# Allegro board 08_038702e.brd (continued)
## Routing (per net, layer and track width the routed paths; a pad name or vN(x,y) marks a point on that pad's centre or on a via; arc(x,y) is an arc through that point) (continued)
VBUS: length 39.7
  L18_SIG w0.203: v1(87.68,36.43) 86.79,36.43 85.9,37.32 85.9,38.21 84.76,39.35 78.03,39.35 72.19,45.19 v1(69.78,45.19)
  BOTTOM w0.14: P1.A1 89.17,34.94 89.17,32 DS1.A
  BOTTOM w0.203: v1(87.68,36.43) 87.81,36.43 89.08,35.16 P1.A1 ; D1.2 69.34,44.76 v1(69.78,45.19)
  BOTTOM w0.381: P1.B1 P1.A1
VCC-1P35: length 98.5
  TOP w0.254: v1(56.99,34.61) 57.22,34.84 C118.1 ; C108.1 49.84,30.21 49.33,29.7 49.33,28.78 v1(49.79,28.31) ; 60.5,45.45 60.12,44.94 60.12,44.18 59.38,43.43 59.14,43.4 v1(57.07,43.4) ; v1(49.79,45.08) 49.72,45 C115.1 ; C116.1 57.96,45.83 v1(57.2,45.07) ; v1(49.79,43.48) 49.67,43.35 C112.1 ; v1(16.18,16.62) 16.55,16.62 16.59,16.66 17.41,16.66 18.59,15.48 39.17,15.48 40.69,17 49.11,17 v1(49.79,16.31) ; C117.1 57.14,38.53 v1(56.99,38.68)
  TOP w0.305: v1(56.19,16.29) 56.38,16.1 C91.1 ; v1(56.97,28.29) 57.84,27.41 C88.1 ; v1(49.79,28.31) 49.59,28.11 C96.1 ; C89.1 58.09,22.46 57.58,21.95 57.27,21.95 C95.1 57.02,21.89 v1(56.99,21.91) ; v1(49.79,20.31) 49.72,20.24 C92.1 ; C97.1 49.67,26.59 49.73,26.65 v1(49.79,26.65) ; C109.1 49.7,34.59 v1(49.79,34.68) ; C94.1 56.31,24.43 ; 56.31,24.43 56.88,25 C87.1 ; 56.31,24.43 v1(56.19,24.31)
  TOP w0.508: v1(53.14,58.15) 53.77,58.15 54.28,58.66 C100.1 54.28,58.91 53.77,59.42 v1(53.14,59.42) ; v1(56.99,19.51) 57.02,19.54 58.47,19.54 ; 39.42,58.78 38.91,58.78 38.66,58.53 v1(38.65,58.53) ; 39.42,58.78 C120.1 ; 39.42,58.78 v1(39.42,57.89) ; v1(49.79,16.31) 49.04,15.56 C192.1 49.07,15.18 49.07,14.08 48.44,13.44 E3.2 ; v1(59.23,38.59) 58.73,39.1 58.47,39.1
  L15_SIG w0.406: v1(53.14,58.15) 53.52,58.15 53.9,58.53 53.9,59.04 53.52,59.42 v1(53.14,59.42) 53.14,59.67 52.63,60.18 49.84,60.18 48.95,61.07 v1(48.31,61.07) v1(47.8,61.07)
  BOTTOM w0.203: v1(50.59,33.94) 50.66,33.94 U3.B2 ; U2.C1 v1(49.79,17.91) ; U2.E9 v1(56.99,19.51) ; U3.A8 55.94,33.33 v1(55.94,33.08) ; U3.A1 49.79,33.08 v1(49.79,33.01) ; v6(56.99,17.94) 56.97,17.94 U2.C9 ; U3.G7 55.36,38.65 v1(55.36,38.71) ; U2.K8 v1(56.19,24.31) ; v1(56.99,34.61) 56.99,34.68 U3.C9 ; U3.C1 v1(49.79,34.68) ; U3.R9 56.99,45.08 57.19,45.08 v1(57.2,45.07) ; U2.G7 v1(55.39,21.11) ; U3.N1 v1(49.79,43.48) ; U3.K2 v1(50.59,41.08) ; U3.H9 v1(56.99,38.68) ; U3.R1 v1(49.79,45.08) ; U2.B2 v1(50.59,17.11) ; U2.R1 v1(49.79,28.31) ; U2.H9 v1(56.99,21.91) ; U2.H2 v1(50.59,21.91) ; v1(56.99,35.54) 56.93,35.54 U3.D9 ; U3.H2 v1(50.59,38.68) ; U2.D9 v1(56.99,18.71) ; U2.N1 49.86,26.65 v1(49.79,26.65) ; U2.N9 v1(56.99,26.71) ; U2.A8 56.19,16.31 v1(56.19,16.29) ; U2.D2 v1(50.59,18.71) ; v1(50.59,35.41) 50.59,35.48 U3.D2 ; U3.K8 v1(56.19,41.08) ; U3.F1 v1(49.79,37.08) ; U2.A1 v1(49.79,16.31) ; U3.E9 v1(56.99,36.28) ; U2.K2 v1(50.59,24.31) ; v1(57.07,43.4) 57.02,43.35 57.01,43.35 56.74,43.08 U3.N9 ; U2.R9 v1(56.97,28.29) ; U2.F1 v1(49.79,20.31)
  BOTTOM w0.254: v1(48.31,61.07) v1(47.8,61.07) 48.06,60.81 48.06,60.36 U14.1
  BOTTOM w0.508: v1(16.18,16.62) 16.56,17 R134.2
VCC-3P3V: length 12.7
  TOP w0.406: C196.1 21.26,59.54 v1(22.02,60.31) ; v1(23.29,60.56) 23.29,60.05 23.61,59.73 E7.2
  TOP w0.508: C196.1 22.06,59.51 v1(22.53,59.04) 23.04,59.54 E7.2
  L17_SIG w0.406: v1(45.39,61.2) 44.5,60.31 v1(42.6,60.31)
  BOTTOM w0.203: 44.46,60.22 R221.1
  BOTTOM w0.254: U14.10 44.46,60.22
  BOTTOM w0.508: v1(42.6,60.31) R222.1 R221.1 ; C43.2 v1(45.39,61.2) ; R178.1 v1(11.86,55.1)
VCC-3P3V-IO: length 35.2
  TOP w0.203: U1.V8 v1(29.22,36.59) ; U1.W8 v1(28.22,36.59) ; U1.U8 v1(30.22,36.59) ; U1.V12 v1(29.22,32.59) ; U1.V14 v1(29.22,29.59)
  TOP w0.305: U11.17 v1(4.64,13.84) ; v1(7.16,10.52) 7.16,11.54 7.55,11.92 U11.21 ; R168.1 v1(34.98,48.62) ; U15.21 19.99,52.69 v1(19.61,53.07) 19.73,53.19 U15.20 ; R167.1 v1(33.33,48.62)
  TOP w0.406: S1.3 v1(4.67,7.81) ; J3.4 v1(1.98,27.26) ; D4.A 43.27,48.75
  TOP w0.508: R8.1 42.47,11.54 41.84,10.9 v1(41.84,9.63) ; 43.27,48.75 v1(43.99,48.75) ; E8.2 31.23,58.59 31.04,58.4 v1(31.04,57.77) ; C41.1 v1(7.16,10.52) ; C197.1 v1(27.57,58.87)
  L3_SIG w0.406: v1(3.61,17) 2.21,18.4 2.21,21.19 3.61,22.59 3.61,25.64 v1(1.98,27.26)
  BOTTOM w0.406: v1(3.23,10.27) 3.86,10.9
  BOTTOM w0.508: C184.1 20.03,53.49 v1(19.61,53.07) ; 3.86,10.9 R109.1 ; C42.1 v1(3.61,17) R4.1 ; C57.1 v1(3.23,9.25)
VCCO-DDR: length 21.2
  TOP w0.203: U1.W22 v1(28.22,21.59) ; U1.H25 v1(40.22,18.59) ; U1.J22 v1(39.22,21.59) ; U1.V25 v1(29.22,18.59) ; U1.N20 v1(35.22,23.59) ; U1.T21 v1(31.22,22.59) ; U1.R24 v1(32.22,19.59) ; U1.M23 v1(36.22,20.59) ; U1.L26 v1(37.22,17.59)
  TOP w0.305: v1(51.61,14.84) C193.1 51.53,15.64 50.98,15.09 v1(50.98,14.84)
  TOP w0.508: C138.1 50.22,5.44 v1(49.46,4.68) ; v1(52.5,4.68) 52.5,4.81 v1(52.76,5.06) 52.76,5.57 C139.1 ; E2.2 v1(49.52,4.11)
  BOTTOM w0.305: C130.1 35.07,23.73 v1(35.22,23.59)
  BOTTOM w0.508: C135.1 v1(19.61,22.97) ; C132.1 v1(19.61,18.4) ; C126.1 v1(27.99,16.49) ; C127.1 v1(36.88,16.36) ; C137.1 v1(34.09,16.49) ; C131.1 v1(41.45,16.36) ; C128.1 v1(29.52,16.49) ; C136.1 v1(38.41,16.36) ; C129.1 v1(32.56,16.49) ; C121.1 v1(31.04,16.49)
VCCO_1P8V: length 14.4
  TOP w0.203: U1.H15 v1(40.22,28.59) ; U1.E14 v1(43.22,29.59) ; U1.B13 v1(46.22,31.59) ; U1.J12 v1(39.22,32.59) ; U1.F11 v1(42.22,33.59) ; U1.A16 v1(47.22,27.59)
  TOP w0.305: 11.8,49.77 v1(14.28,49.77) ; v1(14.28,49.77) 14.4,49.89 v1(14.91,49.89) ; v1(14.28,49.77) v1(14.66,49.38)
  BOTTOM w0.305: C70.1 v1(29.9,44.94) ; C93.1 v1(36.25,44.94) ; C71.1 v1(45.52,44.94) ; C250.1 v1(42.22,30.59) ; C37.1 v1(45.22,30.59) ; C249.1 v1(39.22,30.59) ; C90.1 v1(32.95,44.94) ; C72.1 v1(42.47,44.94) ; C98.1 v1(39.42,44.94)
VCCO_1P8V_EN: length 4.1
  TOP w0.14: U7.24 10.58,46.86 10.34,47.1 10.34,49.7 10.4,49.77
VCCO_12: length 11.7
  TOP w0.203: U1.AA16 v1(26.22,27.59) ; U1.AB13 v1(25.22,31.59) ; U1.AD17 v1(23.22,26.59) ; U1.AC10 v1(24.22,34.59) ; U1.AF11 v1(21.22,33.59) ; U1.AE14 v1(22.22,29.59)
  TOP w0.254: v1(14.62,37.07) 14.56,37.13 14.15,37.13
  TOP w0.406: 14.29,37.07 14.29,37.34 Q11.4 ; 14.29,37.07 v1(14.62,37.07) v1(15.04,37.07) ; 14.29,37.07 Q11.PAD2
  BOTTOM w0.254: v1(14.62,37.07) v1(15.04,37.07)
  BOTTOM w0.508: C160.1 v1(19.61,21.44) ; C144.1 v1(19.61,28.94) ; v1(23.17,16.36) 23.55,15.98 C153.1 ; C157.1 v1(26.21,16.49) ; C146.1 v1(19.61,19.92) ; C111.1 v1(19.61,24.49)
VCCO_12_13_EN: length 30.8
  TOP w0.14: v1(6.78,49) 8.08,47.71 U7.29 ; v1(14.91,36.05) 14.38,35.52 Q11.3 ; Q9.3 17.34,35.18 16.94,34.78 16.56,34.78 v1(16.18,34.4)
  L17_SIG w0.095: 15.55,35.5 16.18,36.13 16.18,36.33 17.03,37.18 17.03,37.46 16.83,37.66 16.83,38.22 17.2,38.59 17.2,42.02 16.44,42.78 12.63,42.78 12.12,43.29 12.12,44.43 11.61,44.94 10.85,44.94 v1(6.78,49) ; 15.55,35.5 15.46,35.5 v1(14.91,36.05) ; 15.55,35.5 15.55,35.03 v1(16.18,34.4)
VCCO_13: length 23.3
  TOP w0.203: U1.Y19 v1(27.22,24.59) ; U1.AE24 v1(22.22,19.59) ; U1.AF21 v1(21.22,22.59) ; U1.AB23 v1(25.22,20.59) ; U1.AC20 v1(24.22,23.59) ; U1.AA26 v1(26.22,17.59)
  TOP w0.254: v1(19.61,34.4) 19.61,36.43 18.15,37.89 ; Q9.PAD2 17.34,37.2 Q9.4 17.55,37.89
  TOP w0.305: 17.2,37.89 18.15,37.89
  BOTTOM w0.254: v1(6.53,21.57) 6.52,21.58 5.14,21.58 4.96,21.4 U21.1 ; 5.26,18.52 3.1,18.52 R57.1
  BOTTOM w0.305: U21.1 4.96,20.34 5.51,19.79 R58.1 ; v1(6.53,21.57) 6.28,21.32 C243.2
  BOTTOM w0.406: 5.26,18.52 5.51,18.78 R58.1 ; 20.12,31.73 v1(19.61,31.73)
  BOTTOM w0.508: C167.1 v1(19.61,26.02) ; C171.1 v1(19.61,34.4) ; C169.1 20.75,15.98 v1(21.13,16.36) ; C186.1 v1(24.69,16.36) ; C185.1 v1(19.61,16.36)
VCCO_33_34: length 22.9
  TOP w0.203: U1.G8 v1(41.22,36.59) ; U1.A6 v1(47.22,38.59) ; U1.K9 v1(38.22,35.59) ; U1.F1 v1(42.22,43.59) ; U1.E4 v1(43.22,40.59) ; v1(18.72,41.64) 18.59,41.51 ; U1.D7 v1(44.22,37.59) ; U1.B3 v1(46.22,41.59) ; U1.J2 v1(39.22,42.59) ; U1.M3 v1(36.22,41.59) ; U1.L6 v1(37.22,38.59) ; U1.C10 v1(45.22,34.59) ; U1.H5 v1(40.22,39.59)
  TOP w0.305: Q10.4 17.2,41 17.71,41.51 18.59,41.51 ; C246.1 54.66,29.32 55.26,29.92 v1(55.68,29.92) U22.14
  TOP w0.508: v1(47.04,44.94) 47.3,45.19 C145.1 ; v1(19.23,41.64) v1(18.72,41.64)
  BOTTOM w0.203: C147.1 v1(47.55,16.36)
  BOTTOM w0.305: C27.1 v1(40.95,44.94) ; C15.1 v1(37.9,44.94) ; C17.1 v1(34.6,44.94) ; C31.1 v1(43.99,44.94) ; C154.1 v1(34.22,38.59) ; C18.1 v1(31.42,44.94)
  BOTTOM w0.508: C114.1 v1(28.37,44.94) ; v1(44.5,16.36) 44.5,15.98 C110.1 ; C28.1 v1(26.85,44.94) ; C99.1 v1(25.33,44.94)
VCCO_33_34_EN: length 24.4
  TOP w0.14: v1(7.16,51.16) 7.8,50.53 7.8,48.88 8.58,48.09 8.58,47.62 8.57,47.61 8.57,46.72 8.58,46.71 U7.28 ; v1(17.58,39.73) 17.39,39.54 Q10.3
  L17_SIG w0.095: v1(7.16,51.16) 8.56,49.77 8.56,48.11 9.36,47.31 10.13,47.31 10.72,46.72 13.64,46.72 16.56,43.8 16.56,43.16 17.71,42.02 17.71,39.86 v1(17.58,39.73)
VCCPCOM-1P8V: length 90.2
  TOP w0.203: U1.G18 v1(41.22,25.59) ; U1.M10 v1(36.22,34.59) ; U1.U9 v1(30.22,35.59) ; U1.T10 v1(31.22,34.59) ; U1.E24 v1(43.22,19.59) ; U1.F21 v1(42.22,22.59) ; U1.K18 v1(38.22,25.59) ; U1.A26 v1(47.22,17.59) ; U1.R9 v1(32.22,35.59) ; U1.V6 v1(29.22,38.59) ; U1.B23 v1(46.22,20.59) ; U1.V10 v1(29.22,34.59) ; U15.14 v1(22.16,56.1) ; U1.R19 v1(32.22,24.59) ; U1.U19 v1(30.22,24.59) ; U1.L19 v1(37.22,24.59) ; U1.C20 v1(45.22,23.59) ; U1.D17 v1(44.22,26.59) ; U1.P10 v1(33.22,34.59) ; U1.T8 v1(31.22,36.59) ; U1.N19 v1(35.22,24.59) ; U15.11 v1(23.66,56.1) ; U1.P8 v1(33.22,36.59) ; U1.N9 v1(35.22,35.59)
  TOP w0.305: C180.1 4.62,49.26 5.51,50.15 v1(6.02,50.15) ; C180.1 4.75,49 5.01,49.26 v1(6.02,49.26) ; C180.1 4.62,48.88 5.01,48.5 5.89,48.5 v1(6.02,48.62) ; U11.5 v1(10.58,15.34) 10.95,14.97 C54.1 ; U15.8 25.68,54.69 v1(25.96,54.97) ; v1(67.62,52.81) 67.87,52.81 68.12,53.07 68.63,53.07 v1(68.76,53.19) 68.54,53.42 68.52,53.42 68.22,53.71 68.22,53.86 68.12,53.96 68.12,55.1 68.62,55.59 U13.B4 ; Q12.1 v1(9.83,50.78) ; v1(24.94,49.89) 24.66,50.17 U15.32 ; R194.1 42.22,14.59 42.22,16.24 42.43,16.45 42.89,16.45 v1(42.98,16.36) ; Q12.2 v1(9.83,50.27) ; U15.28 v1(22.66,49.77) ; U15.30 v1(23.66,49.78) ; Q12.5 v1(11.1,50.27) ; Q12.6 v1(11.1,50.78)
  TOP w0.381: C183.1 23.59,56.18 v1(23.66,56.1)
  TOP w0.406: R7.1 42.04,6.26 ; v1(46.15,3.92) 46.14,3.93 Y1.4
  TOP w0.508: 42.04,6.26 Q5.1 ; R7.1 42.6,5.7 42.6,5.44 v1(42.98,5.06) 43.49,4.55 R3.1 ; R9.1 22.66,47.48 v1(23.17,46.97) ; E1.1 v1(26.15,49.19) ; v1(14.53,15.98) 14.53,15.54 E9.2 ; C39.1 v1(46.15,3.92) ; Y3.4 19.09,57.39 v1(19.74,57.39) 20,57.39 20.51,56.88 22.02,56.88 ; C54.1 C55.1 ; 22.02,56.88 22.52,57.39 C183.1 ; 22.02,56.88 22.16,56.73 v1(22.16,56.1) ; C172.1 45.39,48.37 46.28,49.26 46.28,50.53 47.17,51.42 47.17,52.56 v1(47.42,52.81) 47.72,52.52 S4.3 ; v1(53.65,52.81) 53.94,52.52 S3.3 ; L12.1 v1(51.36,25.13)
  BOTTOM w0.203: 24.44,51.04 24.44,50.4 v1(24.94,49.89)
  BOTTOM w0.254: R32.1 46.53,20.27 v1(46.22,20.59) ; v1(43.22,19.59) 43.07,19.73 R31.1 ; R76.1 46.47,4.24 v1(46.15,3.92)
  BOTTOM w0.305: v1(33.22,34.59) 33.32,34.49 C198.1 ; v1(33.22,36.59) 33.63,36.18 C179.1 ; C175.1 v1(23.22,30.59)
  BOTTOM w0.406: C166.1 v1(24.06,46.84) ; C168.1 v1(19.74,57.39)
  BOTTOM w0.508: v1(47.22,17.59) 46.41,16.78 C176.1 ; C177.1 v1(42.98,16.36) 42.85,16.36 42.22,17 40.44,17 39.93,16.49 C174.1 ; v1(23.17,46.97) 23.76,47.57 C182.1 ; R36.1 4.5,28.3 5.13,28.94 v1(6.28,28.94) ; 62.28,48.24 v1(62.28,47.61) ; R6.1 v1(51.87,60.81) ; C82.1 v1(33.39,57.96) ; 24.44,51.04 C181.1 ; R28.1 65.33,59.42 v1(63.55,59.42) ; C83.1 v1(28.69,60.05)
VCCPINT: length 13.4
  TOP w0.203: U1.R17 v1(32.22,26.59) ; U1.P18 v1(33.22,25.59) ; U1.L17 v1(37.22,26.59) ; U1.N17 v1(35.22,26.59) ; U1.T18 v1(31.22,25.59) ; U1.U17 v1(30.22,26.59)
  TOP w0.508: E4.2 50.53,12.58 v2(51.83,11.28) 51.85,11.28 52,11.14 52,11.12 C191.1
  L2_GND w0.305: v2(52.34,10.52) 52.34,10.05 v3(52.76,9.63) ; v2(51.83,11.28) v3(51.83,9.63)
  BOTTOM w0.102: v1(37.22,26.59) 37.22,26.73 C164.1
  BOTTOM w0.508: C159.1 33.3,25.51 v1(33.22,25.59) ; v1(67.24,3.41) 68,3.41 C173.1 68,2.39 v1(67.24,2.39)
  vias: v2(51.87,10.4) v2(52.74,10.86) v2(52.76,10.4)
VDD_INTERFACE: length 7
  TOP w0.203: v6(60.4,31.29) U17.H12
  TOP w0.254: U22.1 56.94,29.79 57.43,29.31 v1(57.46,29.31)
  TOP w0.305: C245.1 57.39,28.89 57.44,28.93 57.44,29.28 v1(57.46,29.31) ; R306.2 v1(74.22,7.35)
  TOP w0.381: E10.2 v1(73.46,12.94)
  L19_GND w0.305: v4(62.03,20.68) 62.03,20.99 v3(61.74,21.28) ; v3(61.52,22.84) 61.77,22.59 v4(61.77,22.21) ; v3(61.9,24.37) 61.9,24.11 v4(61.77,23.98)
  BOTTOM w0.305: 59.87,31.35 60.34,31.35 v6(60.4,31.29) 60.63,31.06 C355.1 ; 59.87,31.35 C356.1 ; 59.87,31.35 C348.1 ; C354.1 v4(61.77,23.98) ; C357.1 v4(61.77,22.21)
VDDA_GPO: length 102.8
  TOP w0.203: v6(63.6,25.69) U17.B8
  L7_SIG w0.508: v5(85.9,55.99) 88.95,52.94 88.95,46.97 85.52,43.54 85.52,42.27 84.76,41.51 83.75,41.51 81.59,39.35 79.68,39.35 79.05,38.72 v1(78.09,38.72)
  L14_SIG w0.406: 67.87,22.21 66.35,22.21 65.2,23.35 65.2,23.86 64.7,24.37
  L14_SIG w0.508: v5(86.54,56.75) 86.29,56.75 ; 86.29,56.75 86.29,55.99 ; 86.29,56.75 86.29,58.15 v5(86.54,58.4) ; v6(63.6,25.69) 63.6,25.46 64.7,24.37 ; v5(85.9,55.99) 86.29,55.99 ; 86.29,55.99 86.29,53.32 88.44,51.16 88.44,48.75 90.98,46.21 90.98,24.11 85.65,18.78 83.31,18.78 83.27,18.82 82.82,18.82 82.78,18.78 75.36,18.78 73.71,20.43 69.01,20.43 68.63,20.81 68.63,21.44 67.87,22.21
  L19_GND w0.305: v4(78.09,40.05) v1(78.09,38.72)
  BOTTOM w0.305: C359.1 63.56,25.69 v6(63.6,25.69) 64.11,26.21 C319.1 C360.1 ; R67.1 v4(78.09,40.05)
  BOTTOM w0.508: C361.1 v5(86.54,58.4) ; E11.2 85.27,56.62 v5(85.9,55.99) ; C358.1 v5(86.54,56.75)
VDDA_GPO_PWR: length 5.7
  BOTTOM w0.254: U6.1 81.34,58.64 v5(81.59,58.4) 81.33,58.14 U6.2
  BOTTOM w0.508: E11.1 v5(85.27,59.67) ; v1(87.94,47.73) 87.57,47.37 v1(87.32,47.37) JX4.9 ; C200.1 v5(83.24,59.67)
VDDCAP: length 8.1
  TOP w0.254: R30.1 R39.1 1.96,43.61 1.96,43.16 2.81,42.31 3.15,42.31 3.82,41.64 C205.1 3.95,40.88 5.51,40.88 5.67,41.03 U7.39
VIN: length 22
  TOP w0.305: U4.3 63.77,8.62 C62.1 v1(64.1,8.78) ; v1(41.37,53.94) 41.34,53.94 ; 41.34,53.94 40.95,54.34 40.95,54.59 ; 41.34,53.94 U9.8 ; Q13.4 17.09,43.04 Q13.PAD2 ; R43.1 v1(30.66,7.86) ; R56.1 v1(28.25,55.73) ; 59.7,5.32 59.75,5.91 U4.21 ; U4.13 57.58,10.12 57.2,10.5 57.2,11.92 56.82,12.3 v1(56.57,12.3) ; C65.1 56.76,7.2 C66.1 ; U4.17 57.57,8.12 v1(57.33,8.36) 57.59,8.62 U4.16
  TOP w0.406: v1(18.85,45.19) 18.85,45.32 ; 18.85,45.32 v1(18.85,45.7) ; 18.85,45.32 18.66,45.13 C364.1 17.96,44.76 17.52,44.33 17.47,44.33 Q13.4
  TOP w0.508: C36.1 40.6,54.93 40.95,54.59 ; 59.7,5.32 v1(59.7,4.85) ; C65.1 56.86,7.89 v1(56.95,7.98) v1(57.33,8.36) ; TP2.1 55.17,5.2 55.04,5.07 v1(55.04,4.81)
  BOTTOM w0.305: R29.1 60.25,14.97 v1(60,15.22)
  vias: v1(18.47,45.32) v1(18.59,44.81) v1(18.72,42.91) v1(18.85,44.43) v1(19.23,1.63) v1(19.74,1.25) v1(23.8,2.39) v1(25.07,1.38) v1(25.71,1.25)
VIN_EN: length 19
  TOP w0.14: v1(16.82,41.59) 16.82,41.76 17.09,42.03 Q13.3 ; v1(6.66,46.72) 7.16,46.72 7.58,46.3 U7.30
  L17_SIG w0.095: v1(6.66,46.72) 7.67,45.7 7.67,44.81 9.32,43.16 9.32,39.99 9.58,39.73 11.99,39.73 12.63,39.1 13.64,39.1 14.78,40.24 15.47,40.24 v1(16.82,41.59)
1P3_SUPPLY_A: length 86.7
  TOP w0.203: v6(62,25.69) U17.B10 ; v6(69.2,28.89) U17.F2 ; v6(68.4,32.89) U17.K3 ; v6(69.2,28.09) U17.E2 ; v6(62.8,25.69) U17.B9 ; v6(68.4,32.09) U17.J3
  TOP w0.305: U19.12 67.91,12.01 v1(67.45,12.47) ; U19.11 68.56,11.71 v1(69.21,12.36) U19.10
  TOP w0.381: C314.1 65.77,9.82 v1(66.22,9.38) ; U19.13 66.56,9.72 v1(66.22,9.38) ; v1(66.22,9.38) 66.53,9.07 U19.14 ; v1(66.22,9.38) 65.97,9.13 C315.1 ; U19.9 69.86,10.85 70.28,11.27
  TOP w0.508: v1(69.21,12.36) 70.1,12.36 C320.1 70.28,11.27 v1(70.91,10.64) ; C312.1 v1(68.54,14.59) ; C313.1 v1(67.45,12.47)
  L11_POWER w0.203: v6(62,25.69) 62,25.16 62.41,24.75 64.06,24.75 64.57,24.24 64.57,23.1 65.84,21.83 65.84,21.44 65.58,21.19 65.08,21.19 64.44,20.56 64.44,19.29 ; 68,20.81 67.74,21.06 67.74,23.98 67.36,24.37 65.71,24.37 64.82,25.25 63.17,25.25 62.8,25.63 v6(62.8,25.69) ; v6(68.4,32.89) 68.76,33.26 68.76,34.27 69.14,34.65 69.9,34.65 71.3,33.26 74.98,33.26 ; 75.11,28.56 73.84,28.56 73.46,28.94 72.57,28.94 72.06,28.43 71.3,28.43 70.66,29.06 70.16,29.06 69.2,28.11 v6(69.2,28.09) ; 74.98,29.45 74.22,29.45 73.97,29.7 72.32,29.7 71.81,29.19 71.3,29.19 70.79,29.7 70.03,29.7 69.22,28.89 v6(69.2,28.89) ; v6(68.4,32.09) 68.75,32.45 69.22,32.45 69.27,32.49 69.39,32.49 69.64,32.74 69.64,33.12 69.79,33.27 70.27,33.27 71.05,32.49 74.98,32.49
  L15_SIG w0.203: v1(71.3,35.12) 71.3,36.68 72.19,37.57 74.47,37.57 78.28,41.38 78.28,44.81 v3(79.55,46.08)
  L19_GND w0.305: v4(79.55,45.32) v3(79.55,46.08)
  BOTTOM w0.254: U24.18 79.17,44.94 v4(79.55,45.32)
  BOTTOM w0.305: v6(68.4,32.89) 68.44,32.85 C326.1 ; C329.1 68.44,32.05 v6(68.4,32.09) ; C321.1 61.99,25.7 v6(62,25.69)
  BOTTOM w0.508: C328.1 v1(70.41,30.97) ; C327.1 v1(71.3,35.12) ; C323.1 v1(70.54,27.03)
1P3_SUPPLY_B: length 89
  TOP w0.203: v6(69.2,27.29) U17.D2 ; v6(68.4,28.09) U17.E3 ; v6(68.4,27.29) U17.D3 ; v6(67.6,32.89) U17.K4 ; v6(60.4,28.89) U17.F12
  TOP w0.254: C344.1 75.74,9.38 v1(75.87,9.25) ; U20.9 79.51,11.66 v1(79.21,11.96) ; C343.1 75.74,10.14 v1(75.87,10.01)
  TOP w0.305: C337.1 v1(70.92,25.76)
  TOP w0.381: U20.14 76.05,9.07 v1(75.87,9.25) ; U20.11 v1(78.21,11.74) ; U20.13 76.17,9.72 v1(75.87,10.01) ; U20.10 78.86,11.61 v1(79.21,11.96) ; v1(77.27,11.79) 77.56,11.5 U20.12
  L10_POWER w0.254: v6(68.4,28.09) 68.42,28.09 68.84,28.51 70.62,28.51 71.3,29.19 75.49,29.19 ; 68.25,21.83 v1(68.25,23.98) 68.78,24.51 68.78,26.65 68.4,27.03 v6(68.4,27.29) ; v6(67.6,32.89) 67.22,33.27 65.44,33.27 65.08,33.64 65.08,37.45 ; v6(60.4,28.89) 60.66,29.15 60.72,29.15 61.14,29.57 62.03,29.57 62.41,29.95 62.41,34.65 ; 75.49,27.54 72.32,27.54 71.93,27.92 69.78,27.92 69.2,27.34 v6(69.2,27.29)
  L15_SIG w0.203: v1(73,36.18) 73.85,36.18 79.3,41.64 v1(79.3,43.03)
  L19_GND w0.254: v4(73.59,22.21) v3(72.95,22.84)
  BOTTOM w0.102: v4(65.84,37.83) 66.09,38.08 v4(66.09,38.11) 66.06,38.11 v4(65.84,38.34)
  BOTTOM w0.254: U24.19 79.17,44.44 79.55,44.05 79.55,43.29 v1(79.3,43.03) ; v6(60.4,28.89) 60.57,29.06 C330.1 ; v6(68.4,28.09) 68.23,28.09 C4.1 ; C1.1 69.33,27.43 v6(69.2,27.29) ; C325.1 68.53,27.16 v6(68.4,27.29)
  BOTTOM w0.305: L2.1 62.89,40.14 v1(62.16,40.88) 62.16,41.13 v1(62.41,41.38) C24.1 ; C324.1 71.81,37.45 72.47,36.78 v1(72.47,36.43) 72.7,36.43 72.82,36.3 72.87,36.3 v1(73,36.18) 73,36.39 72.95,36.43 72.95,36.78 73.36,37.19 C331.1 ; v1(67.87,40.11) 68,40.24 68,41.26 68.76,42.02 C3.1 ; C334.1 v1(68.25,23.98) ; C19.2 v1(62.79,20.87) ; C335.1 v1(63.68,34.78) ; C2.1 v1(74.41,30.97)
  BOTTOM w0.381: L1.1 61.14,40.16 61.48,40.49 61.77,40.49 v1(62.16,40.88)
  BOTTOM w0.508: C24.1 62.82,41.7 63.3,41.7 ; L11.1 64.95,19.13 64.95,18.4 ; 64.95,18.4 C23.1 ; 64.95,18.4 v1(66.22,18.4) v1(66.98,18.4) 66.98,19.03 67.33,19.38 L10.1 ; 63.3,41.7 63.3,41.13 ; 63.3,41.7 C20.2 ; 63.3,41.13 L2.1 ; 63.3,41.13 62.66,41.13 v1(62.41,41.38) ; L3.1 73.33,17.48 73.71,17.86 v1(73.71,18.02) ; L4.1 70.13,17.35 v1(69.78,17) ; C22.1 C21.1 ; C14.2 68.38,39.48 67.87,39.99 v1(67.87,40.11) 68,40.11 68.25,40.37 C16.2 ; C336.1 v1(72.44,25.13)
  vias: v3(65.08,38.34) v3(65.08,37.7)
9361_XTAL: length 5.2
  TOP w0.14: U17.M12 v6(60.4,34.49) 60.4,35.65 C165.1
  BOTTOM w0.14: v6(60.4,34.49) 60.4,34.5 60.4,35.62 60.12,35.9 C216.2
AD9361_CLK: length 51.2
  TOP w0.14: v5(72.44,56.24) 73.08,56.24 73.95,57.11 U5.1
  L14_SIG w0.095: v1(84.52,25.77) 86.41,27.67 87.94,27.67 88.7,28.43 88.7,44.43 85.9,47.23 85.9,49 84.89,50.02 83.36,50.02 77.52,55.86 72.82,55.86 v5(72.44,56.24)
  BOTTOM w0.14: v5(72.44,56.24) 72.51,56.31 R5.1 ; JX4.63 v1(84.52,25.77)
AUXADC: length 36.8
  TOP w0.14: v6(66.8,33.69) U17.L5
  L7_SIG w0.095: v6(66.8,33.69) 67.04,33.69 67.54,34.19 67.72,34.19 67.9,34.37 67.9,34.55 68.12,34.78 68.76,34.78 73.2,39.22 73.2,44.05 76.51,47.35 76.51,48.37 79.43,51.29 87.43,51.29 87.81,50.91 87.81,48.75 v1(87.23,48.17)
  BOTTOM w0.14: JX4.7 v1(87.23,48.17)
AUXDAC1: length 32.2
  TOP w0.14: v6(68.4,25.69) U17.B3
  L7_SIG w0.095: v6(68.4,25.69) 68.44,25.69 68.89,26.14 71.68,26.14 77.01,31.48 77.01,38.59 80.7,42.27 80.7,45.89 v1(82.98,48.17)
  BOTTOM w0.14: JX4.8 v1(82.98,48.17)
AUXDAC2: length 29.3
  TOP w0.14: v6(68.4,26.49) U17.C3
  L7_SIG w0.095: v6(68.4,26.49) 68.4,26.87 68.7,27.17 68.7,27.23 69.14,27.67 70.41,27.67 74.35,31.6 74.35,35.16 75.64,36.45 75.64,39.88 77.5,41.74 77.74,41.74 77.98,41.98 77.98,42.22 78.03,42.27 78.03,45.45 79.3,46.72 79.55,46.72 79.81,46.97 v1(79.81,47.61)
  BOTTOM w0.14: v1(79.81,47.61) 80.04,47.37 JX4.10
CARRIER_RESET: length 77.1
  TOP w0.14: v1(43.87,12.43) R8.2 43.87,10.9 42.98,10.01 Q5.3
  L3_SIG w0.095: v3(54.06,45.7) 54.28,45.48 55.53,45.48 55.73,45.28 55.73,43.11 56.57,42.27 56.57,33.51 57.33,32.75 57.33,31.7 57.54,31.49 57.54,29.71 57.8,29.45 57.8,29.17 57.33,28.7 57.33,17.76 57.02,17.45 56.85,17.45 55.85,16.46 55.85,16.24 53.77,14.16 53.77,12.17 53.39,11.79 44.5,11.79 v1(43.87,12.43)
  L6_SIG w0.095: v1(32.73,49.55) 33.58,50.4 47.8,50.4 48.95,49.26 v3(49.96,49.26)
  L17_SIG w0.095: v3(54.06,45.7) 53.77,45.99 53.77,47.38 53.43,47.72 53.43,48.33 52.5,49.26 v3(49.96,49.26)
  BOTTOM w0.14: JX1.6 v1(32.73,49.55)
CTRL_IN0: length 25.4
  TOP w0.14: v1(58.73,30.21) 58.46,30.48 U22.2 ; v6(66.8,26.49) U17.C5
  L15_SIG w0.095: v1(58.73,30.21) 57.95,30.98 57.95,33.03 58.72,33.79 58.72,33.88 59.63,34.79 62.9,34.79 63.26,34.44 65.62,34.44 65.87,34.19 66.43,34.19 66.62,33.99 66.92,33.99 67.1,33.82 67.1,33.52 67.3,33.32 67.3,32.77 67.47,32.59 67.65,32.59 68.1,32.14 68.1,31.97 68.27,31.79 68.45,31.79 68.76,31.48 68.76,26.43 68.52,26.19 68.3,26.19 68.23,26.12 67.17,26.12 v6(66.8,26.49)
CTRL_IN1: length 21.9
  TOP w0.14: v1(58.73,30.84) 58.59,30.98 U22.3 ; v6(66,26.49) U17.C6
  L15_SIG w0.095: v1(58.73,30.84) 58.24,31.33 58.24,33 58.94,33.7 58.94,33.72 59.23,34.02 64.82,34.02 65.65,33.19 66.12,33.19 66.3,33.02 66.3,32.77 66.67,32.39 66.92,32.39 67.1,32.22 67.1,31.97 67.47,31.59 67.72,31.59 67.9,31.42 67.9,30.94 68.1,30.74 68.1,27.13 67.87,26.91 66.6,26.91 66.19,26.49 v6(66,26.49)
CTRL_IN2: length 14.9
  TOP w0.14: v6(66,27.29) U17.D6 ; v1(59.23,30.84) 59.09,30.99 59.09,30.99 58.6,31.48 U22.4
  L15_SIG w0.095: v6(66,27.29) 66,27.32 66.47,27.79 66.47,31.24 66.3,31.42 66.12,31.59 65.85,31.59 64.82,32.62 64.55,32.62 64.52,32.59 62.87,32.59 62.5,32.22 62.5,32.07 62.02,31.59 61.87,31.59 61.7,31.42 61.7,31.27 61.39,30.97 59.36,30.97 v1(59.23,30.84)
CTRL_IN3: length 15.5
  TOP w0.14: v6(66.8,27.29) U17.D5 ; U22.5 v1(58.72,31.98)
  L15_SIG w0.095: v6(66.8,27.29) 66.86,27.29 67.24,27.67 67.24,31.28 66.92,31.59 66.67,31.59 66.3,31.97 66.3,32.22 66.12,32.39 65.81,32.39 64.95,33.26 60,33.26 v1(58.72,31.98)
DDR3_A0: length 55.1
  TOP w0.197: R136.1 51.8,43.28 51.61,43.09 51.16,43.09 51.09,43.15 51.09,43.43 51.13,43.47 51.38,43.47 v1(51.39,43.48) ; U1.K22 v1(38.22,21.59)
  L4_SIG w0.14: v1(38.22,21.59) 37.58,22.23 37.58,22.74 37.52,22.8 37.52,23.38 37.58,23.44 37.58,23.74 37.52,23.8 37.52,24.38 37.58,24.44 37.58,24.74 37.52,24.8 37.09,25.23 37.07,25.23 36.85,25.44 36.85,25.46 36.4,25.92 36.37,25.95 36.31,25.95 35.85,26.41 35.85,30.34 35.98,30.46 36.25,30.46 36.5,30.21 36.5,30.08 36.63,29.95 36.88,29.95 37.01,30.08 37.01,30.46 37.12,30.57 37.41,30.57 37.85,30.13 37.85,29.44 38.07,29.23 38.37,29.23 38.85,28.74 38.85,28.44 39.07,28.23 39.37,28.23 39.85,27.74 39.85,27.44 40.07,27.23 40.37,27.23 40.85,26.74 40.85,26.44 41.07,26.23 41.69,26.23 41.96,25.95 47.87,25.95 48.34,25.48 50.67,25.48 50.95,25.76 50.95,25.99 51.39,26.43 v1(51.39,26.65)
  L18_SIG w0.14: v1(51.39,43.48) 51.44,43.48 51.61,43.31 51.76,43.31 52.23,43.78 52.78,43.78 53.9,42.65 53.9,40.24 53.01,39.35 53,39.35 53,38.59 54.03,37.57 54.03,36.94 53.01,35.92 53,35.92 53,31.86 52.88,31.73 52.88,29.66 52.87,29.66 52.87,27.15 52.44,26.71 51.84,26.71 51.78,26.65 v1(51.39,26.65)
  BOTTOM w0.197: v1(51.39,26.65) 51.46,26.65 U2.N3 ; U3.N3 v1(51.39,43.48)
DDR3_A1: length 56.4
  TOP w0.197: U1.K20 v1(38.22,23.59) ; R137.1 53.01,46.08 v1(53.39,45.7)
  L3_SIG w0.14: v1(55.39,27.58) 55.39,27.51 55.81,27.1 55.81,25.86 55.83,25.84 55.83,25.83 56.04,25.62 56.34,25.62 56.55,25.83 56.55,25.85 56.57,25.86 56.57,30.08 54.92,31.73 54.92,42.4 54.66,42.66 54.66,43.93 v3(54.54,44.05)
  L4_SIG w0.14: v1(38.22,23.59) 38.22,23.1 38.53,22.78 38.58,22.74 38.58,22.29 38.79,22.08 39.3,22.08 39.59,22.37 39.59,23.64 40.06,24.11 40.44,24.11 40.69,23.86 40.69,23.47 40.95,23.22 47.8,23.22 47.93,23.35 47.93,23.49 48.07,23.63 48.29,23.63 48.44,23.48 48.44,23.25 48.57,23.12 48.82,23.12 48.9,23.2 48.9,23.5 49,23.6 49.2,23.6 49.33,23.48 49.33,23.22 49.43,23.12 49.91,23.12 50.14,23.35 50.98,23.35 51.23,23.6 51.23,23.73 51.61,24.11 51.74,24.11 51.98,23.88 52.34,23.88 52.36,23.86 52.38,23.86 52.76,23.48 52.88,23.48 53.01,23.6 53.01,23.86 53.13,23.97 53.32,23.97 53.39,23.9 53.39,23.6 53.52,23.48 53.65,23.48 53.77,23.6 53.77,23.73 53.9,23.86 53.9,24.49 53.96,24.56 54.6,24.56 54.79,24.75 54.79,25.25 54.54,25.51 54.03,25.51 53.9,25.64 53.9,26.69 54.07,26.86 54.49,26.86 54.59,26.96 54.59,27.16 54.46,27.29 54.33,27.29 54.2,27.41 54.2,27.58 54.3,27.68 54.94,27.68 55.04,27.58 v1(55.39,27.58)
  L15_SIG w0.14: v3(54.54,44.05) 54.54,44.56 v1(53.39,45.7)
  L19_GND w0.197: v3(54.54,44.05) 54.82,44.05 v4(54.99,43.88)
  BOTTOM w0.197: U2.P7 55.39,27.52 v1(55.39,27.58)
DDR3_A2: length 55.2
  TOP w0.197: U1.N21 v1(35.22,22.59) ; R138.1 51.8,44.62 51.73,44.7 51.45,44.7 51.31,44.56 51.31,44.28 51.38,44.22 v1(51.39,44.22)
  L4_SIG w0.14: v1(35.22,22.59) 35.74,23.11 35.74,24.62 35.36,25 34.98,25 34.61,25.37 34.61,30.59 34.85,30.83 34.85,31.22 34.61,31.46 34.61,31.86 34.86,32.11 35.29,32.11 35.54,31.86 35.74,31.86 35.87,31.99 35.87,32.11 35.98,32.23 37.28,32.23 37.59,31.92 37.59,31.33 37.95,30.96 38.33,30.96 39.34,29.95 39.37,29.95 39.58,29.74 39.58,29.71 40.34,28.95 40.37,28.95 40.58,28.74 40.58,28.71 41.34,27.95 41.37,27.95 41.58,27.74 41.58,27.71 42.34,26.95 48.1,26.95 48.23,27.08 48.57,27.08 48.69,26.95 48.69,26.52 48.82,26.4 49.07,26.4 49.2,26.52 49.2,26.91 49.37,27.08 50.9,27.08 51.39,27.57 v1(51.39,27.58)
  L18_SIG w0.14: v1(51.39,27.58) 51.46,27.51 51.84,27.51 52.34,28.01 52.34,29.88 52.34,29.88 52.34,30.75 52.12,30.97 52.12,33.51 51.75,33.88 51.75,34.03 51.54,34.24 51.32,34.24 51.03,34.53 51.03,35.8 50.73,36.1 50.73,36.56 51.03,36.86 51.03,38.97 50.22,39.78 50.22,40.19 50.95,40.93 50.95,41.36 51.03,41.43 51.03,42.02 50.81,42.24 50.52,42.24 50.09,42.67 50.09,43.16 50.23,43.3 50.23,43.63 50.44,43.84 50.77,43.84 50.85,43.92 51.03,43.92 51.33,44.22 v1(51.39,44.22)
  BOTTOM w0.197: v1(51.39,27.58) 51.39,27.51 U2.P3 ; U3.P3 51.46,44.22 v1(51.39,44.22)
DDR3_A3: length 54.2
  TOP w0.197: R139.1 48.9,44.16 48.9,44.12 49.13,43.89 50.18,43.89 v1(50.59,43.48) ; U1.L22 v1(37.22,21.59)
  L4_SIG w0.14: v1(50.59,26.65) 50.29,26.35 50.01,26.35 49.94,26.29 49.64,26.29 49.58,26.35 49.46,26.35 49.33,26.23 49.33,25.89 49.2,25.76 48.95,25.76 48.19,26.52 47.98,26.52 47.8,26.35 47.49,26.35 47.37,26.23 42.07,26.23 41.85,26.44 41.85,26.58 41.2,27.23 41.07,27.23 40.85,27.44 40.85,27.58 40.2,28.23 40.07,28.23 39.85,28.44 39.85,28.58 39.2,29.23 39.07,29.23 38.85,29.44 38.85,29.63 38.03,30.46 37.9,30.46 37.13,31.23 36.76,31.23 36.63,31.1 36.63,30.97 36.47,30.81 36.27,30.81 35.88,31.21 35.58,31.21 35.1,30.74 35.1,30.21 35.36,29.95 35.37,29.95 35.58,29.74 35.58,26.44 35.37,26.23 35.37,25.95 35.58,25.74 35.58,25.67 36.3,24.95 36.37,24.95 36.63,24.69 36.63,22.46 36.63,22.46 37.12,21.98 37.12,21.69 v1(37.22,21.59)
  L18_SIG w0.14: v1(50.59,26.65) 50.59,26.71 50.93,27.05 51.08,27.05 51.11,27.08 51.54,27.08 51.56,27.05 51.89,27.05 52.61,27.77 52.61,29.77 52.61,29.77 52.61,34.04 51.87,34.78 51.87,35.8 53.01,36.94 53.01,37.7 51.87,38.84 51.87,42.65 51.75,42.77 51.75,42.83 51.53,43.05 51.02,43.05 v1(50.59,43.48)
  BOTTOM w0.197: v1(50.59,26.65) 50.66,26.65 U2.N2 ; U3.N2 v1(50.59,43.48)
DDR3_A4: length 55.7
  TOP w0.197: U1.M20 v1(36.22,23.59) ; v2(56.58,46.23) 56.82,46.46 R140.1
  L2_GND w0.14: v2(56.58,46.23) 56.58,44.61 v3(56.19,44.22)
  L7_SIG w0.14: v1(36.22,23.59) 36.7,23.59 37.07,23.23 37.37,23.23 37.58,23.44 37.58,23.57 38.23,24.23 38.37,24.23 38.58,24.44 38.58,24.74 39.07,25.23 39.37,25.23 39.58,25.44 39.58,26.06 39.73,26.22 40.29,26.22 40.57,25.94 41.05,25.94 41.33,26.22 48,26.22 48.95,27.16 49.64,27.16 49.64,27.15 51.73,27.15 51.87,27.29 51.87,27.79 52.21,28.14 52.41,28.14 52.51,28.04 52.51,27.67 52.41,27.58 52.41,25.6 52.63,25.38 52.88,25.38 53.01,25.51 53.01,27.27 53.14,27.4 53.41,27.4 53.52,27.29 53.52,26.65 53.65,26.52 53.9,26.52 54.03,26.65 54.03,27.15 54.17,27.29 54.66,27.29 54.79,27.16 55.49,27.16 55.9,27.58 v1(56.19,27.58)
  L15_SIG w0.14: v3(56.19,44.22) 57.42,44.22 58.6,43.03 58.6,42.15 58.85,41.89 59.36,41.89 59.87,41.38 59.87,40.62 59.49,40.24 58.98,40.24 58.47,39.73 58.47,33.89 57.71,33.13 57.71,29.57 57.82,29.46 57.82,28.42 56.95,27.54 56.62,27.54 56.58,27.58 v1(56.19,27.58)
  L19_GND w0.14: v3(56.19,44.22) 56.13,44.22 v4(55.79,43.88)
  BOTTOM w0.197: U2.P8 56.19,27.51 v1(56.19,27.58)
DDR3_A5: length 55.1
  TOP w0.197: U1.N22 v1(35.22,21.59) ; R141.1 49.26,45.76 49.56,45.47 49.95,45.47 50.18,45.24 50.18,44.69 50.59,44.28 v1(50.59,44.22)
  L4_SIG w0.14: v1(35.22,21.59) 35.21,21.59 34.72,22.08 34.72,24.75 34.34,25.13 34.34,32.37 35.1,33.13 37.26,33.13 37.85,32.54 37.85,32.41 38.31,31.95 38.37,31.95 38.58,31.74 38.58,31.69 39.31,30.95 39.37,30.95 40.58,29.74 40.58,29.69 41.31,28.95 41.37,28.95 41.58,28.74 41.58,28.69 42.31,27.95 42.37,27.95 42.58,27.74 42.58,27.69 43.04,27.23 47.87,27.23 48.22,27.58 v1(50.59,27.58)
  L18_SIG w0.14: v1(50.59,27.58) 50.64,27.58 50.98,27.92 51.22,27.92 51.24,27.94 51.51,27.94 51.52,27.95 51.54,27.95 51.75,28.16 51.75,28.19 51.87,28.3 51.87,28.41 52.02,28.57 52.02,30.07 51.75,30.33 51.75,33.23 51.47,33.52 51.24,33.52 50.95,33.8 50.95,34.04 50.95,34.09 50.74,34.3 50.69,34.3 50.68,34.32 50.44,34.32 50.23,34.53 50.23,35.53 49.09,36.66 49.09,41.28 49.46,41.64 49.46,42.37 49.07,42.75 49.07,43.27 49.64,43.84 49.76,43.84 49.84,43.92 50.08,43.92 50.38,44.22 v1(50.59,44.22)
  BOTTOM w0.197: U3.P2 50.66,44.22 v1(50.59,44.22) ; U2.P2 50.59,27.51 v1(50.59,27.58)
DDR3_A6: length 54.2
  TOP w0.197: v1(56.19,45.14) 56.13,45.14 55.8,45.47 55.8,46.21 55.3,46.72 R143.1 ; U1.L20 v1(37.22,23.59)
  L7_SIG w0.14: v1(37.22,23.59) 37.77,24.14 37.77,24.87 38.12,25.23 38.37,25.23 38.58,25.44 38.58,25.68 39.12,26.23 39.37,26.23 39.58,26.44 39.58,26.68 39.93,27.03 48.19,27.03 48.57,27.41 48.57,28.05 49.2,28.68 49.2,28.94 48.57,29.57 48.57,29.95 48.95,30.33 49.2,30.33 49.58,30.72 49.58,30.84 49.96,31.22 50.62,31.22 51,30.84 51,28.16 51.22,27.94 51.51,27.94 51.52,27.95 51.54,27.95 51.75,28.16 51.75,28.19 52.32,28.75 52.69,28.75 52.88,28.56 52.88,27.97 53.18,27.67 53.6,27.67 53.9,27.97 53.9,28.37 54.28,28.75 55.75,28.75 56.19,28.31 v1(56.19,28.25)
  L15_SIG w0.14: v1(56.19,45.14) 55.42,44.43 55.42,43.92 55.61,43.74 56.32,43.74 56.36,43.69 56.59,43.69 56.82,43.92 57.2,43.92 58.09,43.03 58.09,42.22 58.1,42.21 58.1,36.7 58.09,36.69 58.09,36.44 58.03,36.38 58.03,33.83 57.34,33.14 57.34,32.38 56.69,31.73 56.69,29.33 56.63,29.26 56.63,28.75 56.19,28.31 v1(56.19,28.25)
  BOTTOM w0.197: v1(56.19,45.14) 56.19,45.08 U3.R8 ; U2.R8 56.13,28.25 v1(56.19,28.25)
DDR3_A7: length 54.8
  TOP w0.197: U1.J21 v1(39.22,22.59) ; R144.1 50.2,46.77 50.2,45.72 50.59,45.33 v1(50.59,45.14)
  L4_SIG w0.14: v1(50.59,28.31) 50.95,27.95 51.54,27.95 51.75,27.74 51.75,25.76 51.48,25.49 51.21,25.49 50.95,25.23 50.95,24.96 50.74,24.75 48.43,24.75 47.93,25.25 47.39,25.25 47.37,25.23 41.07,25.23 40.85,25.44 40.85,25.46 40.69,25.63 40.69,25.9 40.44,26.14 40.15,26.14 39.85,26.44 39.85,26.86 39.48,27.23 39.17,27.23 39.04,27.1 39.04,27.03 38.95,26.94 38.75,26.94 38.47,27.23 38.22,27.23 37.9,26.91 37.64,26.91 37.52,27.03 37.52,27.29 37.58,27.35 37.58,29 37.39,29.19 37.01,29.19 36.76,28.94 36.76,26.52 37.33,25.95 37.37,25.95 37.58,25.74 37.58,25.7 38.15,25.13 38.28,25.13 38.79,24.62 38.79,23.1 39.22,22.67 v1(39.22,22.59)
  L18_SIG w0.14: v1(50.59,45.14) 50.53,45.14 50.22,45.45 49.58,45.45 48.31,44.18 48.31,34.71 49.38,33.64 49.52,33.64 49.64,33.52 49.94,33.52 50.15,33.3 50.15,32.49 49.96,32.3 49.96,30.97 51.03,29.9 51.03,28.73 50.61,28.31 v1(50.59,28.31)
  BOTTOM w0.197: U3.R2 50.59,45.08 v1(50.59,45.14) ; U2.R2 v1(50.59,28.31)
DDR3_A8: length 52.7
  TOP w0.197: v1(56.19,45.88) 56.2,45.88 56.2,46.32 56.06,46.46 R145.1 ; U1.T20 v1(31.22,23.59)
  L14_SIG w0.14: v1(56.19,29.18) 55.33,28.68 55.17,28.68 54.98,28.49 54.92,28.18 54.82,27.96 54.53,27.67 52.25,27.67 51.66,27.08 35.06,27.08 34.47,27.67 33.96,27.67 33.45,27.16 32.06,27.16 31.68,26.78 31.68,24.11 31.22,23.65 v1(31.22,23.59)
  L18_SIG w0.14: v1(56.19,45.88) 56.62,45.45 57.58,45.45 58.09,44.95 58.09,43.68 58.75,43.02 58.75,40.35 59.87,39.22 59.87,37.83 59.49,37.45 59.49,34.78 58.68,33.97 58.68,33.9 57.96,33.19 57.96,30.84 56.57,29.45 56.47,29.45 v1(56.19,29.18)
  BOTTOM w0.197: U2.T8 56.19,29.11 v1(56.19,29.18) ; U3.T8 v1(56.19,45.88)
DDR3_A9: length 52.5
  TOP w0.197: v1(51.39,45.14) 51.33,45.14 50.98,45.49 50.98,46.04 50.98,46.04 R146.1 ; U1.U20 v1(30.22,23.59)
  L14_SIG w0.14: v1(30.22,23.59) 29.64,24.16 29.64,27.54 30.15,28.05 32.44,28.05 32.69,28.3 32.69,28.94 32.95,29.19 34.47,29.19 34.72,28.94 34.72,28.43 35.1,28.05 49.55,28.05 49.64,27.95 51.03,27.95 v1(51.39,28.31)
  L18_SIG w0.14: v1(51.39,28.31) 51.75,28.68 51.75,29.69 50.98,30.46 50.98,33.13 50.95,33.15 50.95,33.23 50.74,33.44 50.52,33.44 50.23,33.73 50.23,33.95 49.94,34.24 49.36,34.24 48.58,35.02 48.58,43.81 49.41,44.64 50.95,44.64 51.39,45.08 v1(51.39,45.14)
  BOTTOM w0.197: U3.R3 51.39,45.08 v1(51.39,45.14) ; U2.R3 v1(51.39,28.31)
DDR3_A10: length 54.8
  TOP w0.197: v1(55.39,41.88) 54.88,41.36 R147.1 ; U1.M22 v1(36.22,21.59)
  L4_SIG w0.14: v1(55.39,25.05) 55.39,24.84 53.65,23.1 51.12,23.1 51.11,23.08 50.33,23.08 50.1,22.85 47.46,22.85 47.37,22.95 41.07,22.95 40.97,22.85 40.46,22.85 40.37,22.95 40.07,22.95 39.85,22.74 39.85,21.62 39.42,21.19 37.9,21.19 37.77,21.32 37.52,21.32 37.39,21.19 37.39,20.94 37.64,20.68 37.64,20.3 37.52,20.17 37.01,20.17 36.63,19.79 36.63,19.29 36.37,19.03 34.83,19.03 34.6,19.26 34.6,19.79 34.85,20.05 36.25,20.05 36.76,20.56 36.76,20.68 36.37,21.06 36.35,21.06 36.22,21.2 v1(36.22,21.59)
  L18_SIG w0.14: v1(55.39,25.05) 55.39,25.11 54.92,25.59 54.92,28.82 55.03,28.94 55.03,29.33 55.3,29.59 55.3,30.21 57.43,32.34 57.43,33.41 57.46,33.44 57.46,33.64 57.96,34.14 57.96,39.35 56.63,40.68 56.63,41.23 56.66,41.25 56.66,41.88 56.57,41.96 56.57,42.19 56.1,42.66 55.64,42.66 55.42,42.43 55.42,41.9 v1(55.39,41.88)
  BOTTOM w0.197: v1(55.39,25.05) 55.33,25.05 U2.L7 ; v1(55.39,41.88) U3.L7
DDR3_A11: length 56.7
  TOP w0.197: R148.1 53.77,46.7 55.33,45.14 v1(55.39,45.14) ; U1.H21 v1(40.22,22.59)
  L3_SIG w0.14: v1(55.39,28.25) 55.17,28.03 55.17,27.92 54.92,27.67 54.92,26.93 54.79,26.8 54.39,26.8 54.26,26.93 54.26,27.51 54.77,28.03 54.77,28.03 54.79,28.05 54.79,29.19 54.65,29.33 54.65,42.02 54.15,42.51 54.15,44.7 54.54,45.08 55.33,45.08 v1(55.39,45.14)
  L4_SIG w0.14: v1(40.22,22.59) 40.72,22.08 47.36,22.08 47.61,21.83 47.61,21.13 47.93,20.81 48.06,20.81 48.19,20.94 48.19,21.44 47.93,21.7 47.93,22.21 48.19,22.46 48.57,22.46 48.69,22.33 48.69,21.83 48.57,21.7 48.57,20.94 48.69,20.81 48.82,20.81 49.33,21.31 49.33,22.33 49.58,22.58 50.21,22.58 50.45,22.82 51.22,22.82 51.23,22.83 54.28,22.83 54.41,22.96 54.41,23.35 54.54,23.48 54.79,23.48 54.92,23.35 54.92,22.97 55.06,22.83 55.28,22.83 55.81,23.35 55.81,26.08 55.62,26.27 55.42,26.27 55.3,26.14 55.3,25.82 55.11,25.64 54.92,25.64 54.79,25.76 54.79,26.78 55.17,27.16 55.55,27.16 55.81,27.41 55.81,27.9 55.46,28.25 v1(55.39,28.25)
  BOTTOM w0.197: v1(55.39,28.25) 55.33,28.25 U2.R7 ; v1(55.39,45.14) 55.39,45.08 U3.R7
DDR3_A12: length 52.2
  TOP w0.197: v1(55.37,43.38) 54.81,42.82 54.81,42.23 54.38,41.8 R149.1 ; U1.P20 v1(33.22,23.59)
  L14_SIG w0.14: v1(55.39,26.65) 54.92,26.65 54.79,26.52 54.79,25.64 54.66,25.51 53.77,25.51 53.65,25.64 53.65,26.09 53.46,26.27 53.27,26.27 53.14,26.14 53.14,24.75 53.01,24.62 52.76,24.62 52.55,24.82 52.55,25.26 52.51,25.31 52.51,26.01 52.41,26.11 52.21,26.11 52,25.89 52,25.76 51.74,25.51 50.22,25.51 49.84,25.13 38.15,25.13 38.15,25.14 37.58,25.71 37.58,25.74 37.37,25.95 36.07,25.95 35.85,25.74 35.85,25.72 35.35,25.22 34.95,25.22 34.59,24.85 34.59,24.36 33.82,23.59 v1(33.22,23.59)
  L18_SIG w0.14: v1(55.37,43.38) 55.32,43.33 55.32,43.06 55.46,42.93 56.21,42.93 56.23,42.91 56.25,42.91 56.51,42.65 56.57,42.65 56.84,42.38 56.84,42.07 56.95,41.96 56.95,41.66 57.26,41.34 57.37,41.15 57.37,41.08 58.41,40.05 58.41,34.01 57.7,33.3 57.7,31.21 55.75,29.27 55.75,27.08 55.39,26.71 v1(55.39,26.65)
  BOTTOM w0.197: U2.N7 55.33,26.65 v1(55.39,26.65) ; v1(55.37,43.38) 55.29,43.38 U3.N7
DDR3_A13: length 54.7
  TOP w0.197: U1.J20 v1(39.22,23.59) ; R150.1 51.74,46.23 v1(51.39,45.88)
  L3_SIG w0.14: v1(51.39,45.88) 51.39,45.65 51.03,45.29 51.03,44.99 50.62,44.58 50.24,44.58 49.33,43.67 49.33,43.03 48.19,41.89 48.19,39.86 49.43,38.61 49.43,38.53 49.64,38.32 49.73,38.32 49.84,38.21 50.41,38.21 50.44,38.24 51.76,38.24 52.66,37.34 52.66,32.9 52.3,32.54 52.3,31.27 51.39,30.37 v1(51.39,29.11)
  L4_SIG w0.14: v1(51.39,29.11) 52.12,28.38 52.12,26.02 52.63,25.51 52.63,25.13 52.77,24.98 53,24.98 53.09,25.08 53.09,26.15 53.22,26.27 53.39,26.27 53.52,26.15 53.52,24.37 53.39,24.24 52.76,24.24 52.63,24.37 52.63,24.49 52.38,24.75 51.58,24.75 50.71,23.88 49.56,23.88 49.07,24.37 48.69,24.37 48.46,24.14 48.18,24.14 47.95,24.37 47.68,24.37 47.42,24.11 41.07,24.11 40.82,24.37 40.82,24.87 40.57,25.13 40.06,25.13 39.8,25.38 39.8,26.02 39.6,26.22 39.07,26.22 38.88,26.41 38.57,26.41 38.43,26.27 38.43,25.97 38.79,25.61 38.79,25.38 39.04,25.13 39.17,25.13 39.3,25 39.42,25 39.68,24.75 39.68,24.44 39.22,23.98 v1(39.22,23.59)
  BOTTOM w0.197: U2.T3 v1(51.39,29.11) ; U3.T3 v1(51.39,45.88)
DDR3_A14: length 53.5
  TOP w0.197: R151.1 54.54,46.74 v1(55.39,45.88) ; U1.R20 v1(32.22,23.59)
  L7_SIG w0.14: v1(55.39,29.18) 55.39,29.69 55.17,29.92 55.17,31.73 54.64,32.26 54.64,33.24 55.03,33.62 55.03,34.03 55.24,34.24 55.65,34.24 55.83,34.42 55.83,34.83 56.04,35.04 56.45,35.04 56.63,35.22 56.63,35.63 56.63,35.63 56.63,35.69 56.84,35.9 57.13,35.9 57.15,35.92 57.33,35.92 57.58,36.18 57.58,37.7 58.88,39 58.88,40.16 58.23,40.81 57.24,40.81 57.14,40.72 56.82,40.72 56.63,40.91 56.63,41.23 56.69,41.29 56.69,41.76 56.19,42.27 56.19,42.43 55.81,42.82 55.81,45.47 v1(55.39,45.88)
  L14_SIG w0.14: v1(32.22,23.59) 33.45,24.24 33.85,24.73 34.67,25.58 35.02,25.93 35.95,26.22 36.63,26.22 36.64,26.23 37.52,26.23 49,26.15 50.44,26.28 50.74,26.28 50.75,26.27 51.24,26.27 51.24,26.28 51.49,26.28 55.17,27.08 55.64,27.23 55.81,27.54 55.81,28.05 55.83,28.11 55.83,28.4 56.06,28.68 56.57,28.94 56.57,29.32 56.31,29.57 56.19,29.57 55.95,29.51 v1(55.39,29.18)
  BOTTOM w0.197: U3.T7 v1(55.39,45.88) ; v1(55.39,29.18) 55.39,29.11 U2.T7
DDR3_BA0: length 55.2
  TOP w0.197: R152.1 50.03,42.11 v1(50.59,42.68) ; U1.U22 v1(30.22,21.59)
  L3_SIG w0.14: v1(50.59,42.68) 50.32,42.4 50.22,42.4 48.92,41.1 48.92,39.71 49.4,39.22 51.39,39.22 53.13,37.48 53.13,32.99 52.57,32.43 52.57,27.22 51.62,26.28 51.24,26.28 51.24,26.27 50.98,26.27 50.62,25.91 v1(50.59,25.91)
  L7_SIG w0.14: v1(30.22,21.59) 30.58,21.23 30.58,18.22 30.85,17.95 30.85,17.44 31.07,17.23 31.58,17.23 31.93,16.87 33.39,16.87 33.84,17.33 33.84,18.01 33.85,18.01 33.85,18.79 34.28,19.23 35.37,19.23 35.58,19.44 35.58,20.06 35.84,20.33 35.84,20.73 35.87,20.75 35.87,21.43 35.85,21.44 35.85,21.81 36.27,22.23 37.37,22.23 37.58,22.44 37.58,22.46 38.07,22.95 38.47,22.95 38.74,23.23 39.37,23.23 39.58,23.44 39.58,23.74 40.07,24.23 40.37,24.23 40.58,24.44 40.58,24.46 41.07,24.96 43.7,24.96 43.95,25.22 47.25,25.22 47.48,25.22 47.68,25.01 48.07,25.01 48.44,25.38 50.06,25.38 v1(50.59,25.91)
  BOTTOM w0.197: U3.M2 v1(50.59,42.68) ; U2.M2 v1(50.59,25.91)
DDR3_BA1: length 54.5
  TOP w0.197: U1.T22 v1(31.22,21.59) ; v2(54.68,43.53) 54.54,43.67 54.21,43.67 53.96,43.43 53.96,43.15 R153.1
  L2_GND w0.14: v1(56.17,43.38) 56.01,43.53 55.73,43.53 55.52,43.74 55.22,43.74 55.01,43.53 v2(54.68,43.53)
  L14_SIG w0.14: v1(56.19,26.65) 55.92,26.38 55.92,26.22 54.3,24.6 53.88,24.6 53.52,24.24 53.52,23.1 53.31,22.89 47.89,22.89 47.55,23.22 37.01,23.22 36.58,23.66 36.58,23.74 36.33,23.98 35.1,23.98 34.85,23.74 34.85,23.73 34.72,23.6 34.72,23.44 34.24,22.96 31.93,22.96 31.58,22.6 31.58,21.95 v1(31.22,21.59)
  L15_SIG w0.14: v1(56.19,26.65) 56.19,27.03 55.81,27.41 55.81,29.45 56.19,29.83 56.19,31.76 57.08,32.65 57.08,33.26 57.58,33.76 57.58,36.56 57.84,36.81 57.84,42.1 57.24,42.69 56.99,42.69 56.69,42.4 55.82,42.4 55.68,42.54 55.68,42.81 55.81,42.93 56.08,42.93 56.17,43.02 v1(56.17,43.38)
  BOTTOM w0.197: U2.N8 56.13,26.65 v1(56.19,26.65) ; v1(56.17,43.38) 56.09,43.38 U3.N8
DDR3_BA2: length 59.5
  TOP w0.197: U1.R22 v1(32.22,21.59) ; R154.1 51.8,42.38 51.69,42.27 51.21,42.27 51.11,42.37 51.11,42.65 51.13,42.68 51.39,42.68 v1(51.39,42.68)
  L7_SIG w0.14: v1(51.39,25.91) 51.03,26.28 48.95,26.28 48.63,25.95 44.07,25.95 43.59,25.47 43.59,25.45 43.37,25.23 40.37,25.23 40.09,24.95 40.07,24.95 39.85,24.74 39.85,24.71 39.09,23.95 39.07,23.95 38.85,23.74 38.85,23.71 38.37,23.23 37.74,23.23 37.48,22.96 36.97,22.96 36.95,22.95 36.07,22.95 35.85,22.74 35.85,22.58 35.58,22.3 35.58,20.44 35.16,20.02 34.69,20.02 33.58,18.9 33.58,18.3 33.58,18.3 33.58,17.44 33.37,17.23 32.07,17.23 31.58,17.71 31.58,17.74 31.37,17.95 31.34,17.95 30.85,18.44 30.85,20.62 30.85,20.74 31.07,20.95 31.09,20.95 31.73,21.59 v1(32.22,21.59)
  L17_SIG w0.14: v1(51.39,25.91) 51.42,25.89 52.25,25.89 52.38,26.02 54.37,26.02 v1(54.41,26.05)
  BOTTOM w0.127: U3.M3 52.75,42.28
  BOTTOM w0.197: U2.M3 v1(51.39,25.91) ; v1(54.41,26.05) 54.37,26.05 53.65,26.78 53.65,30.08 53.39,30.33 52.91,30.33 52.9,30.35 51.98,30.35 51.74,30.59 51.74,31.48 52,31.73 53.39,31.73 53.65,31.99 53.65,34.53 53.9,34.78 54.03,34.78 54.28,35.03 54.28,36.94 54.03,37.19 53.9,37.19 53.65,37.45 53.65,41.51 52.88,42.28 52.75,42.28 ; v1(51.39,42.68) U3.M3
DDR3_CAS#: length 58.4
  TOP w0.197: R159.1 51.8,40.81 51.67,40.67 51.13,40.67 51.06,40.75 51.06,41.03 51.08,41.05 51.37,41.05 v1(51.39,41.08) ; U1.Y23 v1(27.22,20.59)
  L18_SIG w0.14: v1(52.19,24.31) 51.83,23.95 49.64,23.95 47.37,26.23 40.31,26.23 39.58,25.49 39.58,25.44 39.37,25.23 39.27,25.23 38.58,24.54 38.58,24.44 38.37,24.23 34.07,24.23 34.05,24.24 33.33,24.24 32.58,23.49 32.58,23.44 32.37,23.23 32.31,23.23 31.58,22.49 31.58,22.44 31.37,22.23 31.31,22.23 30.66,21.57 30.66,20.43 30.41,20.17 27.99,20.17 27.58,20.59 v1(27.22,20.59)
  BOTTOM w0.127: U3.K3 51.86,40.75 52.63,40.75
  BOTTOM w0.197: 52.63,40.75 52.88,40.49 52.88,32.75 52.63,32.49 51.23,32.49 50.98,32.24 50.98,29.95 51.23,29.7 52.63,29.7 52.88,29.45 52.88,24.49 53.65,23.73 53.65,22.87 53.37,22.59 52.94,22.59 52.63,22.89 52.63,23.88 v1(52.19,24.31) U2.K3 ; v1(51.39,41.08) U3.K3
DDR3_CK_N: length 57.5
  TOP w0.152: U1.P21 v1(33.22,22.59) ; R142.2 57.2,41.09 56.67,40.56 55.87,40.56 55.39,41.03 v1(55.39,41.08)
  L14_SIG w0.13: v1(55.39,24.31) 55.63,24.31 55.81,24.14 55.81,24.01 55.67,23.87 55.4,23.87 55.23,24.04 54.41,24.04 54.03,23.66 54.03,19.77 53.8,19.54 53.12,19.54 52.89,19.77 52.89,22.19 52.45,22.62 49.51,22.62 49.07,22.19 49.07,21.32 48.83,21.07 48.41,21.07 48.19,21.3 48.19,22.23 47.81,22.6 47.71,22.6 47.36,22.95 34.98,22.95 34.34,22.59 v1(33.22,22.59)
  L18_SIG w0.13: v1(55.39,24.31) 55.32,24.24 54.66,24.24 54.29,24.61 54.29,24.61 53.92,24.98 53.92,25 53.92,25.28 54.05,25.4 54.05,28.32 54.15,28.43 54.15,29.28 54.3,29.43 54.43,29.43 54.64,29.64 54.64,29.78 54.77,29.91 54.77,29.93 54.89,30.06 54.89,30.14 54.92,30.17 54.92,30.97 55.55,31.6 56.57,32.62 56.57,33.13 57.7,34.26 57.7,38.98 56.05,40.64 55.84,40.64 v1(55.39,41.08)
  BOTTOM w0.152: U3.K7 v1(55.39,41.08) ; U2.K7 v1(55.39,24.31)
DDR3_CK_P: length 58
  TOP w0.152: U1.R21 v1(32.22,22.59) ; v1(55.39,40.28) 55.68,39.99 56.19,39.99 56.48,40.28 56.95,40.28 57.2,40.02 R142.1
  L14_SIG w0.13: v1(55.39,23.51) 55.12,23.79 55.12,23.78 54.61,23.78 54.61,23.79 54.51,23.79 54.28,23.56 54.28,19.67 53.9,19.29 53.01,19.29 52.63,19.67 52.63,22.08 52.34,22.37 49.62,22.37 49.33,22.08 49.33,21.19 48.95,20.81 48.31,20.81 47.93,21.19 47.93,22.12 47.71,22.35 47.48,22.35 47.36,22.23 47.32,22.23 47.3,22.21 32.11,22.21 32.02,22.3 32.02,22.48 32.12,22.59 v1(32.22,22.59)
  L18_SIG w0.13: v1(55.39,23.51) 55.39,23.74 55.17,23.96 54.58,23.96 54.04,24.5 54.04,24.5 53.67,24.87 53.67,24.89 53.67,24.89 53.67,25.38 53.79,25.51 53.79,28.43 53.9,28.53 53.9,29.4 53.92,29.43 53.92,29.94 54.13,30.14 54.28,30.14 54.66,30.59 54.66,31.08 56.31,32.73 56.31,33.23 57.45,34.37 57.45,38.87 56.04,40.28 v1(55.39,40.28)
  BOTTOM w0.152: U3.J7 v1(55.39,40.28) ; U2.J7 v1(55.39,23.51)
DDR3_CKE: length 58.9
  TOP w0.197: U1.U21 v1(30.22,22.59)
  L7_SIG w0.14: v3(56.99,41.08) 58.04,41.08 58.09,41.13 59.74,41.13 60.38,40.49 60.38,39.2 58.09,36.91 58.09,25.38 57.02,24.31 v1(56.99,24.31)
  L14_SIG w0.14: v1(30.22,22.59) 30.79,22.02 30.79,21.44 31.17,21.06 47.3,21.06 48.41,19.95 51.07,19.95 51.87,19.15 52.4,19.15 52.64,18.9 54.03,18.9 54.66,19.54 54.66,21.98 v1(56.99,24.31)
  L19_GND w0.14: v4(56.59,40.68) v3(56.99,41.08)
  BOTTOM w0.197: v4(56.59,40.68) 58.97,40.68 R160.1 ; U2.K9 v1(56.99,24.31)
DDR3_CS#: length 57
  TOP w0.197: v1(50.59,41.88) 50.22,41.51 49.46,41.51 49.07,41.13 R163.1 ; U1.Y21 v1(27.22,22.59)
  L3_SIG w0.14: v1(50.59,25.11) 50.59,25.12 50.98,25.51 51.74,25.51 53.01,26.78 53.01,32.49 53.39,32.87 53.39,37.62 51.41,39.61 50.4,39.61 49.82,40.18 49.82,40.33 49.61,40.54 49.46,40.54 49.25,40.75 49.25,41.05 50.09,41.89 50.58,41.89 v1(50.59,41.88)
  L18_SIG w0.14: v1(27.22,22.59) 27.72,22.08 29.22,22.08 29.58,22.44 29.58,22.52 30.28,23.23 30.37,23.23 30.58,23.44 30.58,23.52 31.28,24.23 31.37,24.23 31.58,24.44 31.58,24.52 32.28,25.23 32.37,25.23 32.85,25.72 32.85,25.74 33.13,26.02 38.15,26.02 38.85,26.72 38.85,26.74 39.07,26.95 39.09,26.95 39.85,27.72 39.85,27.74 40.16,28.05 47.7,28.05 47.96,28.3 47.96,29.52 48.29,29.85 48.85,29.85 49.19,29.51 49.19,26.52 v1(50.59,25.11)
  BOTTOM w0.197: U3.L2 v1(50.59,41.88) ; U2.L2 v1(50.59,25.11)
DDR3_DM0: length 43.3
  TOP w0.197: U1.G24 v1(41.22,19.59)
  L7_SIG w0.14: v1(55.39,19.51) 55.8,19.92 57.58,19.92 57.84,20.17 58.22,20.17 59.38,21.34 59.38,21.34 59.6,21.55 59.6,21.55 60.12,22.08 65.2,22.08 65.46,22.33 65.46,22.97 65.2,23.22 59.62,23.22 57.95,21.55 55.15,21.55 54.28,20.68 49.2,20.68 48.06,19.54 48.06,17.51 47.42,16.87 42.85,16.87 42.5,17.23 42.07,17.23 41.85,17.44 41.85,17.87 41.58,18.14 41.58,19.16 41.22,19.52 v1(41.22,19.59)
  BOTTOM w0.197: U2.E7 v1(55.39,19.51)
DDR3_DM1: length 43.9
  TOP w0.197: U1.K25 v1(38.22,18.59)
  L17_SIG w0.14: v1(38.22,18.59) 38.66,18.14 39.55,18.14 39.8,18.4 39.8,18.9 40.06,19.16 42.34,19.16 42.6,19.41 42.6,19.92 42.34,20.17 39.8,20.17 39.68,20.05 39.68,19.41 39.42,19.16 35.99,19.16 35.74,18.9 35.74,15.22 36.12,14.84 36.63,14.84 36.88,15.09 36.88,15.86 36.74,16 36.73,16 36.5,16.23 36.5,16.87 36.76,17.13 36.76,18.02 36.88,18.14 37.52,18.14 37.77,17.89 37.77,17 37.41,16.64 37.41,16.34 37.9,15.86 37.9,15.86 38.28,15.48 39.17,15.48 39.55,15.86 39.55,16.11 39.93,16.49 40.57,16.49 40.95,16.11 40.95,15.81 41.28,15.48 41.75,15.48 42.09,15.81 42.09,16.49 42.35,16.75 49.94,16.75 50.23,17.04 50.23,17.26 50.44,17.48 50.69,17.48 51.36,18.14 51.36,18.68 v1(51.39,18.71)
  BOTTOM w0.197: U2.D3 v1(51.39,18.71)
DDR3_DM2: length 46.1
  TOP w0.197: U1.P26 v1(33.22,17.59)
  L7_SIG w0.14: v1(55.39,36.21) 55.08,36.53 54.72,36.53 54.52,36.32 54.52,36.18 54.28,35.94 54.14,35.94 53.87,35.68 53.87,35.19 54.15,34.91 54.53,34.91 54.79,34.65 54.79,34.27 54.53,34.02 54.15,34.02 53.9,33.76 53.9,29.57 53.65,29.32 53.27,29.32 53.01,29.57 53.01,32.49 52.75,32.75 52.27,32.75 51.63,32.11 50.24,32.11 50.08,31.95 49.58,31.95 49.2,32.33 48.44,32.33 48.06,31.95 48.06,28.68 47.42,28.05 40.16,28.05 39.58,27.46 39.58,27.44 39.37,27.23 39.34,27.23 38.58,26.46 38.58,26.44 38.37,26.23 38.34,26.23 37.58,25.46 37.58,25.44 37.37,25.23 37.34,25.23 36.85,24.74 36.85,24.46 36.34,23.95 36.07,23.95 35.85,23.74 35.85,23.46 35.58,23.19 35.07,23.19 34.85,22.97 34.85,20.81 33.58,19.54 33.58,19.44 33.37,19.23 33.27,19.23 32.82,18.78 32.82,17.99 v1(33.22,17.59)
  BOTTOM w0.197: v1(55.39,36.21) 55.39,36.28 U3.E7
DDR3_DM3: length 43.8
  TOP w0.197: U1.V26 v1(29.22,17.59)
  L15_SIG w0.14: v1(51.39,35.41) 50.88,35.92 50.09,35.92 49.2,35.03 43.11,35.03 42.58,34.5 42.58,34.44 42.37,34.23 42.3,34.23 41.58,33.5 41.58,33.44 41.37,33.23 41.3,33.23 40.69,32.62 40.69,28.43 40.21,27.95 40.07,27.95 39.85,27.74 39.85,27.59 39.21,26.95 39.07,26.95 38.85,26.74 38.85,26.59 38.21,25.95 38.07,25.95 37.85,25.74 37.85,25.59 37.39,25.13 34.98,25.13 34.72,24.87 34.72,24.49 34.22,23.98 34.22,18.97 34.5,18.68 35.04,18.14 35.23,18.14 35.62,17.75 35.62,17.45 35.3,17.13 28.17,17.13 27.85,17.44 27.85,17.74 28.07,17.95 28.37,17.95 28.43,17.89 28.92,17.89 v1(29.22,17.59)
  BOTTOM w0.197: v1(51.39,35.41) 51.39,35.48 U3.D3
DDR3_DQ0: length 43.6
  TOP w0.197: U1.J26 v1(39.22,17.59)
  L17_SIG w0.14: v1(52.19,19.51) 52.55,19.15 52.55,14.59 52.3,14.33 42.98,14.33 42.72,14.59 42.72,15.22 42.98,15.48 50.98,15.48 51.23,15.73 51.23,17 51.83,17.6 51.83,19.32 51.64,19.51 51.34,19.51 50.9,19.08 50.44,19.08 50.15,18.79 50.15,18.56 49.87,18.28 49.64,18.28 49.43,18.06 49.43,17.86 48.79,17.23 39.58,17.23 v1(39.22,17.59)
  BOTTOM w0.197: U2.E3 v1(52.19,19.51)
DDR3_DQ1: length 43.4
  TOP w0.197: U1.F25 v1(42.22,18.59)
  L17_SIG w0.14: v1(55.39,20.31) 55.76,20.68 57.46,20.68 57.71,20.43 57.71,14.97 57.96,14.71 58.6,14.71 58.85,14.97 58.85,16.11 59.11,16.36 63.04,16.36 63.3,16.62 63.3,18.02 63.04,18.28 61.23,18.28 61.23,18.27 59.11,18.27 58.85,18.52 58.85,20.68 57.96,21.57 57.16,21.57 57.14,21.55 55.15,21.55 53.91,20.31 53.51,20.31 53.14,20.68 48.95,20.68 48.31,20.05 43.89,20.05 43.58,19.74 43.58,19.44 43.37,19.23 42.85,19.23 v1(42.22,18.59)
  BOTTOM w0.197: U2.F7 v1(55.39,20.31)
DDR3_DQ2: length 43.4
  TOP w0.197: U1.J25 v1(39.22,18.59)
  L7_SIG w0.14: v1(39.22,18.59) 39.23,18.59 39.8,18.02 39.8,17.25 40.06,17 41.84,17 42.62,16.22 42.62,16.21 42.83,16 42.83,16 43.11,15.73 46.92,15.73 47.42,15.22 53.18,15.22 53.39,15.44 53.39,15.74 53.18,15.95 48.16,15.95 47.93,16.19 47.93,16.51 48.16,16.75 51.36,16.75 51.61,17 53.85,17 54.23,17.38 54.23,20.1 54.03,20.3 53.27,20.3 53.01,20.05 53.01,18.65 52.76,18.4 52.39,18.4 52.34,18.35 48.86,18.35 48.69,18.52 48.69,19.29 49.33,19.92 50.2,19.92 v1(50.59,20.31)
  BOTTOM w0.197: U2.F2 v1(50.59,20.31)
